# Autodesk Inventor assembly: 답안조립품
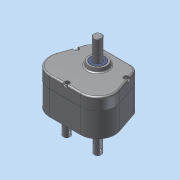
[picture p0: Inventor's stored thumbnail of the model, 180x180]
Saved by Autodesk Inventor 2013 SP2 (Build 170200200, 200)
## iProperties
Created: 2014-12
Part Number: 답안조립품
Document SubType Name: Assembly
Designer: dgall
Author: dgall
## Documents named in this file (13)
- C:\Documents and Settings\dgall\바탕 화면\441208V1029\답안조립품.iam
- C:\Documents and Settings\dgall\바탕 화면\441208V1029\본체.ipt
- C:\Documents and Settings\dgall\바탕 화면\441208V1029\오일시일-D-15.ipt
- C:\Documents and Settings\dgall\바탕 화면\441208V1029\커버.ipt
- C:\Documents and Settings\dgall\바탕 화면\441208V1029\오일시일-D-17.ipt
- C:\Documents and Settings\dgall\바탕 화면\441208V1029\베어링- 6203.ipt
- C:\Documents and Settings\dgall\바탕 화면\441208V1029\베어링- 6202.ipt
- C:\Documents and Settings\dgall\바탕 화면\441208V1029\메인축.ipt
- C:\Documents and Settings\dgall\바탕 화면\441208V1029\멈춤링.ipt
- C:\Documents and Settings\dgall\바탕 화면\441208V1029\서브축.ipt
- C:\Documents and Settings\dgall\바탕 화면\441208V1029\키5x5.ipt
- C:\Documents and Settings\dgall\바탕 화면\441208V1029\메인기어.ipt
- C:\Documents and Settings\dgall\바탕 화면\441208V1029\서브기어.ipt
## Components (12 placed, 5 different names)
1. KS B 2804 D D - 15 30 7:1
2. KS B 2804 D D - 15 30 7:2
3. KS B 2804 D D - 17 30 8:1
4. KS B 2023 6203 - 17 x 40 x 12:1
5. KS B 2023 6203 - 17 x 40 x 12:2
6. KS B 2023 6202 - 15 x 35 x 11:1
7. KS B 2023 6202 - 15 x 35 x 11:2
8. KS B 2023 6203 - 17 x 40 x 12:3
9. KS B 2023 6203 - 17 x 40 x 12:4
10. KS B 1336 17 x 1:1
11. KS B 1336 17 x 1:2
12. KS B 1336 17 x 1:3
